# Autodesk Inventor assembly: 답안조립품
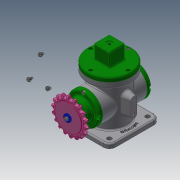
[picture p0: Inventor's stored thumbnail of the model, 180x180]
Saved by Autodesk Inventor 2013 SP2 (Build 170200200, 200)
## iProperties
Created: 2021-03
Part Number: 답안조립품
Document SubType Name: Assembly
Designer: kumcom13
Author: kumcom13
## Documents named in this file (19)
- C:\Users\kumcom13\Desktop\710306V1026\답안조립품.iam
- C:\Users\kumcom13\Desktop\710306V1026\본체.ipt
- C:\Users\kumcom13\Desktop\710306V1026\E-링.ipt
- C:\Users\kumcom13\Desktop\710306V1026\덮개.ipt
- C:\Users\kumcom13\Desktop\710306V1026\뒤커버.ipt
- C:\Users\kumcom13\Desktop\710306V1026\링크.ipt
- C:\Users\kumcom13\Desktop\710306V1026\멈춤나사 M3.ipt
- C:\Users\kumcom13\Desktop\710306V1026\베어링 17 x 40 x 12.ipt
- C:\Users\kumcom13\Desktop\710306V1026\볼트 M4 x 8.ipt
- C:\Users\kumcom13\Desktop\710306V1026\볼트 M4 x 10.ipt
- C:\Users\kumcom13\Desktop\710306V1026\스프로킷.ipt
- C:\Users\kumcom13\Desktop\710306V1026\슬라이더.ipt
- C:\Users\kumcom13\Desktop\710306V1026\앞커버.ipt
- C:\Users\kumcom13\Desktop\710306V1026\오일 실 17 30 8.ipt
- C:\Users\kumcom13\Desktop\710306V1026\와셔 4x16.ipt
- C:\Users\kumcom13\Desktop\710306V1026\클레비스 핀 6 x 22.ipt
- 클레비스 핀 6 x 22.ipt
- C:\Users\kumcom13\Desktop\710306V1026\키 4 x 4 x 12.ipt
- C:\Users\kumcom13\Desktop\710306V1026\편심축.ipt
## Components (1 placed, 1 different names)
1. E-링:1
